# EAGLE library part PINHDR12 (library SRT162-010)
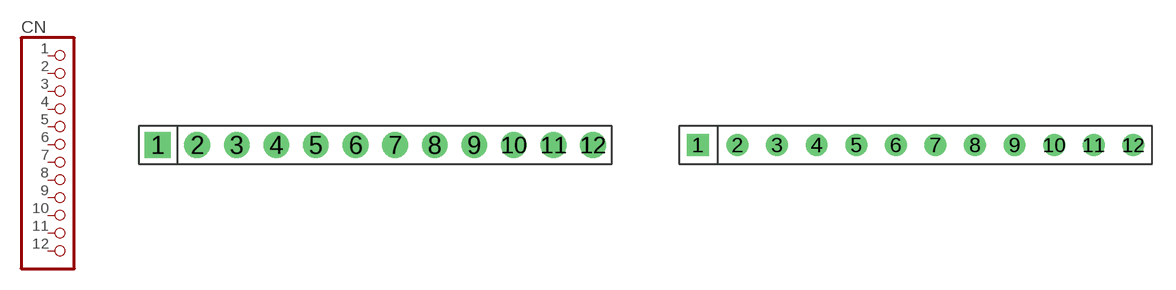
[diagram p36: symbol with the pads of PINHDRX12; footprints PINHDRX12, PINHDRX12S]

Designator prefix CN

## PINHDR12  [PINHDRX12]
1  1  pas
2  2  pas
3  3  pas
4  4  pas
5  5  pas
6  6  pas
7  7  pas
8  8  pas
9  9  pas
10  10  pas
11  11  pas
12  12  pas

## PINHDR12S  [PINHDRX12S]
Pads as for PINHDRX12

## PINHDR120.8  [PINHDRX12_0.8]
Pads as for PINHDRX12

## PINHDR120.8NM  [PINHDRX12_0.8NM]
Pads as for PINHDRX12

## PINHDR120.8NMC  [PINHDRX12_0.8NMC]
Pads as for PINHDRX12

## PINHDR120.8C  [PINHDRX12_0.8C]
Pads as for PINHDRX12

## Footprint PINHDRX12 (pad centres in mm)
drill 1.1 square: 1 -13.97,0
drill 1.1 round: 2 -11.43,0; 3 -8.89,0; 4 -6.35,0; 5 -3.81,0; 6 -1.27,0; 7 1.27,0; 8 3.81,0; 9 6.35,0; 10 8.89,0; 11 11.43,0; 12 13.97,0

## Footprint PINHDRX12S (pad centres in mm)
drill 0.9 square: 1 -13.97,0
drill 0.9 round: 2 -11.43,0; 3 -8.89,0; 4 -6.35,0; 5 -3.81,0; 6 -1.27,0; 7 1.27,0; 8 3.81,0; 9 6.35,0; 10 8.89,0; 11 11.43,0; 12 13.97,0

## Footprint PINHDRX12_0.8 (pad centres in mm)
drill 0.8 square: 1 -13.97,0
drill 0.8 round: 2 -11.43,0; 3 -8.89,0; 4 -6.35,0; 5 -3.81,0; 6 -1.27,0; 7 1.27,0; 8 3.81,0; 9 6.35,0; 10 8.89,0; 11 11.43,0; 12 13.97,0

## Footprint PINHDRX12_0.8NM (pad centres in mm)
drill 0.8 round: 1 -13.97,0; 2 -11.43,0; 3 -8.89,0; 4 -6.35,0; 5 -3.81,0; 6 -1.27,0; 7 1.27,0; 8 3.81,0; 9 6.35,0; 10 8.89,0; 11 11.43,0; 12 13.97,0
